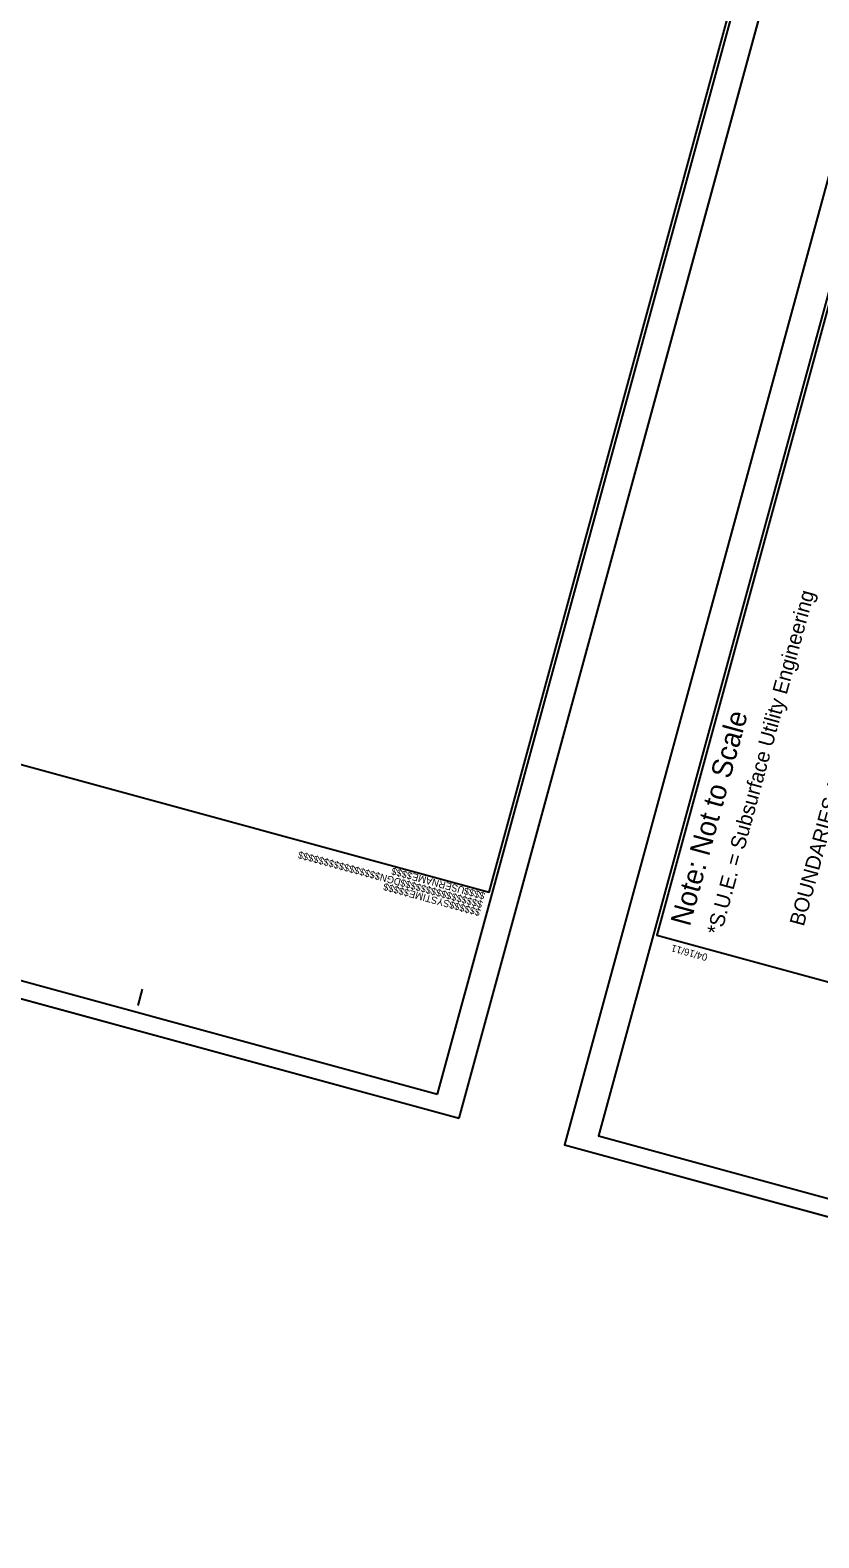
# Model space of a CAD drawing. Extents: x 2076126 to 2079903, y 925480 to 928006.
# Drawn here: x 2076866 to 2077447, y 925785 to 926895 of the extents above; entities that cross this region are included whole.
import ezdxf

# ---------------------------------------------------------------- set-up
doc = ezdxf.new("R2010")
doc.units = 0
for name, color, linetype in [('Sheet Cutting Line CELL', 7, 'Continuous'), ('Sheet Plan CELL', 7, 'Continuous'), ('Sheet Plot Border Inside CELL', 7, 'Continuous'), ('Sheet Plot Border Outside CELL', 7, 'Continuous'), ('Sheet Summary Guardrail CELL', 7, 'Continuous'), ('Sheet Symbology CELL', 7, 'Continuous')]:
    doc.layers.add(name, color=color, linetype=linetype)

msp = doc.modelspace()

# ---------------------------------------------------------------- linework, layer by layer
at = {"layer": 'Sheet Cutting Line CELL'}
for p, q in [((2077182.3, 926093.6), (2077625.3, 927717.7)), ((2077702.9, 927698.6), (2077259.8, 926074)), ((2076125.9, 926381.7), (2077182.3, 926093.6)), ((2077259.8, 926074), (2078321, 925784.5))]:
    msp.add_line(p, q, dxfattribs=at)
at = {"layer": 'Sheet Plan CELL'}
for p, q in [((2077204.4, 926260.1), (2077204.4, 926260.1)), ((2076945.8, 926176.7), (2076949.1, 926188.8))]:
    msp.add_line(p, q, dxfattribs=at)
msp.add_lwpolyline([(2076586.1, 927983.6), (2076191.4, 926536.4), (2077204.4, 926260.1), (2077599.1, 927707.3)], close=True, dxfattribs=at)
at = {"layer": 'Sheet Plot Border Inside CELL'}
for points in [[(2077166.4, 926111.4), (2077604.8, 927718.7), (2076587, 927996.3), (2076148.6, 926389)], [(2078302.8, 925803), (2078741.3, 927410.7), (2077723.4, 927688.4), (2077284.9, 926080.6)]]:
    msp.add_lwpolyline(points, close=True, dxfattribs=at)
at = {"layer": 'Sheet Plot Border Outside CELL'}
for points in [[(2077182.3, 926093.6), (2077625.3, 927717.7), (2076568.9, 928005.9), (2076125.9, 926381.7)], [(2078321, 925784.5), (2078764.2, 927409.2), (2077702.9, 927698.6), (2077259.8, 926074)]]:
    msp.add_lwpolyline(points, close=True, dxfattribs=at)
at = {"layer": 'Sheet Symbology CELL'}
msp.add_lwpolyline([(2077722.6, 927675.6), (2077327.9, 926228.5), (2078339.9, 925952.5), (2078734.6, 927399.6)], close=True, dxfattribs=at)

# ---------------------------------------------------------------- texts
at = {"layer": 'Sheet Plan CELL'}
for s, p in [('$$$$$$$$$$$$$$$$DGN$$$$$$$$$$$$$$$$', (2077200.1, 926253.4)), ('$$$$USERNAME$$$$', (2077201.8, 926259.7)), ('$$$$$$SYSTIME$$$$$', (2077198.5, 926247.5))]:
    msp.add_text(s, height=5.25, rotation=164.7434, dxfattribs=at).set_placement(p)
at = {"layer": 'Sheet Summary Guardrail CELL'}
msp.add_text('04/16/11', height=5.25, rotation=164.7434, dxfattribs=at).set_placement((2077365.7, 926214.4))
at = {"layer": 'Sheet Symbology CELL'}
for s, height, p in [('*S.U.E. = Subsurface Utility Engineering', 11, (2077375.2, 926228.1)), ('BOUNDARIES AND PROPERTY:', 11, (2077436.1, 926234.5)), ('Note: Not to Scale', 15, (2077352.2, 926234.4))]:
    msp.add_text(s, height=height, rotation=74.7434, dxfattribs=at).set_placement(p)

doc.saveas('drawing.dxf')
